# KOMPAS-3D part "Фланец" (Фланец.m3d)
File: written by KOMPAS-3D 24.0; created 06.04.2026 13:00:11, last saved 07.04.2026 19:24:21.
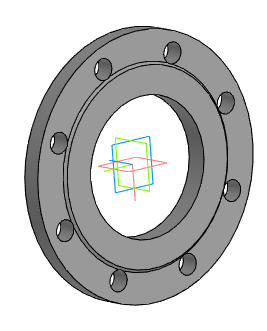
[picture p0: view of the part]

Document properties: Автор: R2D2; Полное имя файла: E:\Работа\Зайцев\Солянка\VSR1-13V-PED-F Клапан запорно-регулирующий DN.ru\DN150\исходные материалы\Фланец.m3d

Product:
- Component [standard]: (unnamed)  | qty 1  | Материал: ВЧ40 ГОСТ 7293-85 (density 7200 kg/m3); Масса: 8.2; additional columns: 150-16-01-2-B-ВЧ40-II-dв 170,5; Фланец; ГОСТ 33259-2015
- Part/product: Фланец
    Масса: 7.499952

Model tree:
1. Эскиз:8
2. Элемент выдавливания:8
     Расстояние 2 = 24
3. Эскиз:10  (with: Грань.Элемент выдавливания:8, Ребро.Элемент выдавливания:8)
4. Элемент выдавливания:12
5. Массив по концентрической сетке:1  (with: Элемент выдавливания:12, Эскиз:10)  (8 pattern instances)
     Шаг 2 = 360

Expressions: v520+50
Referenced files in C:\Program Files\ASCON\KOMPAS-3D v24\Libs\PolynomLib\DATA\vault\Methods\Kompas\3D\: PLib_Flange_GOST_33259_1401.m3d
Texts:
  BOSimple***Material:38d6725a-5efe-48e1-b177-a7817acb862a
  BOSimple***PART:0b6dcd4e-dc17-8056-cc88-7e6d855381ce***SHORTLOC:B6A6_23E38AE8DB154823[II;2;Круглый;150;16;170,5;0;ВЧ40 ГОСТ 7293-85]
  Ch34
  Плоскость XY.Начало координат
  Ось Z.Начало координат
  Plane ZX. Origin
  Плоскость ZX.Начало координат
